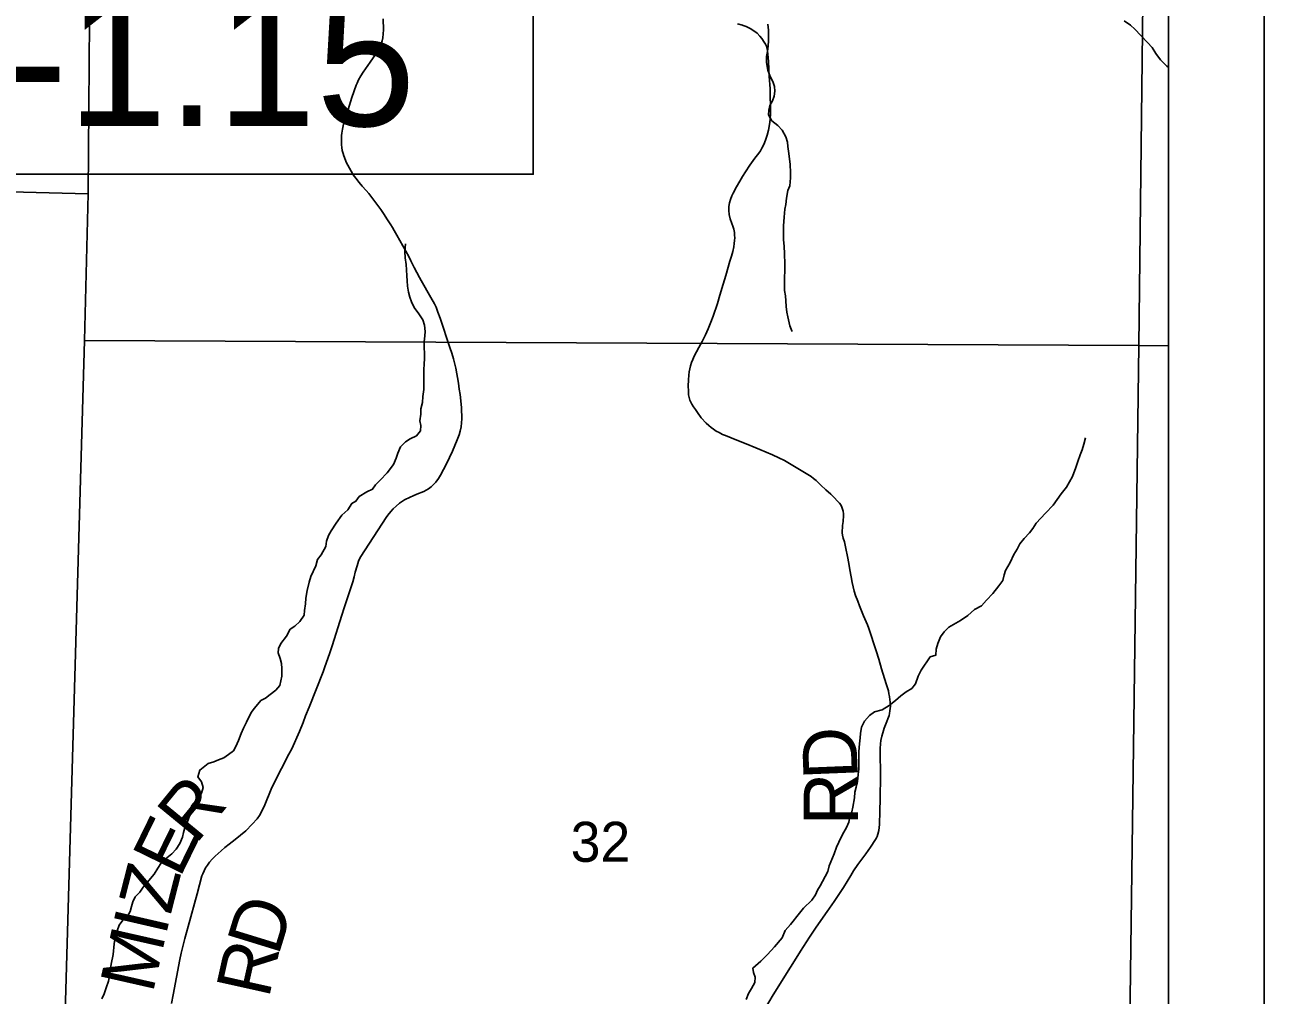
# Model space of a CAD drawing. Extents: x 0 to 34, y 0 to 22.
# Drawn here: x 24.203 to 25.5, y 15.795 to 16.809 of the extents above; entities that cross this region are included whole.
import ezdxf

# ---------------------------------------------------------------- set-up
doc = ezdxf.new("R2010")
doc.units = 0
for name, color, linetype in [('GM_X_Corporation', 7, 'Continuous'), ('GM_X_Minor_River', 7, 'Continuous'), ('GM_X_Section_Text', 7, 'Continuous'), ('GM_X_Township_Road', 7, 'Continuous'), ('GM_X_Township_Road_Text', 7, 'Continuous'), ('SH_Data', 7, 'Continuous'), ('SH_Text', 7, 'Continuous')]:
    doc.layers.add(name, color=color, linetype=linetype)

msp = doc.modelspace()

# ---------------------------------------------------------------- linework, layer by layer
at = {"layer": 'GM_X_Corporation'}
msp.add_lwpolyline([(20.2208, 16.9558), (20.1987, 15.2691), (20.203, 14.81), (20.2016, 14.6512), (20.2571, 14.6508), (21.1282, 14.6279), (21.314, 14.623), (22.3464, 14.612), (22.9003, 14.6033), (24.2301, 14.5912), (24.2265, 14.4444), (24.4406, 14.442), (25.338, 14.4317), (25.4, 14.4307), (25.4, 19.0068)], dxfattribs=at)
for points in [[(23.2763, 17.6399), (24.2773, 17.6357), (24.2765, 17.4936), (24.2698, 16.6327), (23.7676, 16.6453), (23.2579, 16.628)], [(24.2765, 17.4936), (25.3807, 17.4896), (25.3688, 16.474), (24.2658, 16.4792), (24.2698, 16.6327)], [(25.4, 16.4736), (25.4, 17.4893), (25.3807, 17.4896), (25.3688, 16.474)], [(23.2579, 16.628), (23.7676, 16.6453), (24.2698, 16.6327), (24.2658, 16.4792), (24.2407, 15.6067), (23.2418, 15.623)], [(24.2658, 16.4792), (25.3688, 16.474), (25.3552, 15.4512), (24.2392, 15.4615), (24.2407, 15.6067)], [(25.4, 15.4506), (25.4, 16.4736), (25.3688, 16.474), (25.3552, 15.4512)]]:
    msp.add_lwpolyline(points, close=True, dxfattribs=at)
at = {"layer": 'GM_X_Minor_River'}
for points in [[(24.9807, 16.81), (24.9815, 16.8036), (24.9815, 16.7926), (24.9812, 16.7872), (24.9804, 16.7812), (24.9793, 16.7762), (24.9793, 16.7698), (24.9809, 16.7618), (24.9832, 16.7553), (24.9859, 16.75), (24.9878, 16.7447), (24.9882, 16.7398), (24.9874, 16.7348), (24.9855, 16.7299), (24.9829, 16.7249), (24.9818, 16.72), (24.9814, 16.7151), (24.9849, 16.709), (24.9913, 16.7041), (24.9959, 16.6991), (24.9997, 16.6923), (25.0012, 16.6866), (25.0016, 16.682), (25.0024, 16.6771), (25.0032, 16.6718), (25.004, 16.6631), (25.0044, 16.6547), (25.0044, 16.6494), (25.0037, 16.641), (25.0018, 16.6361), (25.0003, 16.6281), (24.9996, 16.6213), (24.9984, 16.6167), (24.9977, 16.6083), (24.997, 16.5992), (24.997, 16.5848), (24.9978, 16.5776), (24.9982, 16.5703), (24.9986, 16.5589), (24.9986, 16.5532), (24.9983, 16.5441), (24.9983, 16.5316), (24.9991, 16.5259), (24.9995, 16.5206), (24.9999, 16.5149), (25.0007, 16.5088), (25.0015, 16.5039), (25.0038, 16.4947), (25.006, 16.4894), (25.0063, 16.4888)], [(25.3535, 16.8133), (25.36, 16.8088), (25.3645, 16.8046), (25.371, 16.7981), (25.3779, 16.7909), (25.3828, 16.7856), (25.3866, 16.7792), (25.3916, 16.7727), (25.3981, 16.7659), (25.4, 16.7647)], [(24.6018, 16.5803), (24.6011, 16.5723), (24.6015, 16.5655), (24.6023, 16.5586), (24.6027, 16.553), (24.6031, 16.5469), (24.6035, 16.5416), (24.6039, 16.5359), (24.6047, 16.5298), (24.6062, 16.5245), (24.6081, 16.5195), (24.6108, 16.5138), (24.6157, 16.507), (24.6199, 16.5009), (24.6215, 16.4952), (24.6222, 16.4888), (24.6219, 16.4842), (24.6211, 16.4778), (24.6212, 16.4721), (24.6216, 16.4652), (24.6216, 16.4607), (24.6212, 16.4542), (24.6209, 16.4493), (24.6209, 16.428), (24.6198, 16.4208), (24.6194, 16.4143), (24.6179, 16.4078), (24.6176, 16.4021), (24.6168, 16.3953), (24.6176, 16.3904), (24.6173, 16.3847), (24.6131, 16.3797), (24.6067, 16.3763), (24.6017, 16.3732), (24.5964, 16.3679), (24.5938, 16.3614), (24.5919, 16.3561), (24.5893, 16.3497), (24.5825, 16.3409), (24.5753, 16.3333), (24.5704, 16.3283), (24.5673, 16.3238), (24.5613, 16.3211), (24.5533, 16.3162), (24.5499, 16.3112), (24.5454, 16.3089), (24.5412, 16.3021), (24.5351, 16.2967), (24.5291, 16.2884), (24.5238, 16.2804), (24.5212, 16.2754), (24.5189, 16.2694), (24.5182, 16.264), (24.5133, 16.2553), (24.5095, 16.2503), (24.508, 16.2435), (24.5027, 16.2325), (24.5008, 16.2264), (24.4989, 16.218), (24.4974, 16.21), (24.4971, 16.204), (24.496, 16.1971), (24.4956, 16.1922), (24.4911, 16.1853), (24.4858, 16.1807), (24.4812, 16.1773), (24.4771, 16.1701), (24.4714, 16.1625), (24.4687, 16.1572), (24.4684, 16.1526), (24.4707, 16.1469), (24.4718, 16.1416), (24.4722, 16.1363), (24.4723, 16.1283), (24.4704, 16.1184), (24.4662, 16.1138), (24.4602, 16.1093), (24.4552, 16.1054), (24.4503, 16.1028), (24.4439, 16.0948), (24.4401, 16.0902), (24.4352, 16.0803), (24.4322, 16.0739), (24.4299, 16.0682), (24.4269, 16.0609), (24.4243, 16.0548), (24.4216, 16.0503), (24.4167, 16.0465), (24.4118, 16.043), (24.4061, 16.0407), (24.4011, 16.0388), (24.3951, 16.0369), (24.3867, 16.0301), (24.3845, 16.0232), (24.3883, 16.0179), (24.3902, 16.0118), (24.3883, 16.0061), (24.3823, 15.9981), (24.3781, 15.9932), (24.3766, 15.9882), (24.3762, 15.9829)], [(25.1615, 16.1694), (25.1653, 16.1747), (25.1702, 16.1796), (25.1824, 16.1865), (25.1899, 16.1918), (25.1971, 16.1979), (25.2043, 16.2017), (25.2096, 16.2078), (25.2161, 16.2147), (25.2225, 16.2227), (25.2266, 16.2284), (25.2278, 16.2341), (25.2293, 16.2386), (25.2342, 16.247), (25.238, 16.2554), (25.2417, 16.2611), (25.2444, 16.2668), (25.2489, 16.2721), (25.2546, 16.2782), (25.258, 16.2828), (25.2614, 16.2881), (25.2712, 16.2987), (25.2792, 16.3071), (25.2875, 16.3189), (25.2932, 16.3258), (25.2996, 16.3372), (25.303, 16.3463), (25.3052, 16.3528), (25.3075, 16.3596), (25.3094, 16.3649), (25.3113, 16.371), (25.3131, 16.3775)], [(24.958, 15.7904), (24.9606, 15.7965), (24.9637, 15.8019), (24.9671, 15.8079), (24.9674, 15.8136), (24.9659, 15.8186), (24.9651, 15.8231), (24.9734, 15.8304), (24.9803, 15.8372), (24.9878, 15.8452), (24.9958, 15.8548), (24.9988, 15.8624), (25.0045, 15.8688), (25.0139, 15.8806), (25.0181, 15.8856), (25.0268, 15.894), (25.0306, 15.8997), (25.0328, 15.9046), (25.0355, 15.9092), (25.0378, 15.9137), (25.0434, 15.924), (25.0449, 15.9301), (25.0502, 15.9426), (25.0525, 15.9495), (25.0551, 15.9548), (25.0589, 15.9628), (25.063, 15.97), (25.0653, 15.9757), (25.0664, 15.9814), (25.0687, 15.9864), (25.0698, 15.9913), (25.0713, 16.0012), (25.0717, 16.0069), (25.0732, 16.0122), (25.0747, 16.0183), (25.0754, 16.0255), (25.0761, 16.0309), (25.0761, 16.0366), (25.0761, 16.0495), (25.0768, 16.0575), (25.0772, 16.0639), (25.0775, 16.0685), (25.0787, 16.075), (25.0817, 16.0814), (25.087, 16.0871), (25.0923, 16.091), (25.1003, 16.0932), (25.1078, 16.0978), (25.1143, 16.1028), (25.12, 16.1077), (25.1253, 16.1119), (25.1313, 16.1153), (25.1351, 16.1203), (25.1381, 16.1283), (25.1411, 16.1347), (25.1506, 16.1484), (25.1566, 16.1503), (25.157, 16.1564), (25.1585, 16.1625), (25.1615, 16.1694)], [(24.3762, 15.9829), (24.3732, 15.9753), (24.371, 15.9696), (24.3695, 15.9647), (24.3683, 15.9601), (24.3657, 15.9533), (24.3619, 15.9475), (24.3574, 15.9426), (24.3521, 15.9384), (24.3456, 15.9323), (24.3426, 15.9277), (24.3388, 15.9213), (24.3316, 15.9125), (24.3271, 15.9076), (24.3237, 15.9026), (24.3188, 15.8977), (24.3165, 15.8923), (24.315, 15.8874), (24.3135, 15.8821), (24.3109, 15.8775), (24.3059, 15.8733), (24.3022, 15.868), (24.2999, 15.8619), (24.298, 15.8554), (24.2969, 15.8486), (24.2958, 15.8372), (24.2939, 15.8273), (24.2928, 15.8201), (24.292, 15.8151), (24.2909, 15.8094), (24.2887, 15.8026), (24.2864, 15.7961), (24.2841, 15.7908)]]:
    msp.add_lwpolyline(points, dxfattribs=at)
at = {"layer": 'GM_X_Township_Road'}
for points in [[(24.357, 15.7861), (24.3585, 15.795), (24.3656, 15.8321), (24.367, 15.8386), (24.3709, 15.8542), (24.3743, 15.8667), (24.3837, 15.9009), (24.3888, 15.9195), (24.3897, 15.9217), (24.391, 15.9248), (24.3926, 15.928), (24.3944, 15.9307), (24.3966, 15.9337), (24.3993, 15.9368), (24.4026, 15.9401), (24.4089, 15.9458), (24.4127, 15.9491), (24.4172, 15.9527), (24.4235, 15.9577), (24.4345, 15.9665), (24.4414, 15.9734), (24.4465, 15.9793), (24.4489, 15.9827), (24.4513, 15.9871), (24.4544, 15.9938), (24.4611, 16.0101), (24.4644, 16.0168), (24.4798, 16.0467), (24.4827, 16.0524), (24.4907, 16.0705), (24.4945, 16.0799), (24.4972, 16.0867), (24.5009, 16.096), (24.5156, 16.133), (24.5174, 16.1379), (24.5222, 16.1518), (24.5249, 16.1601), (24.535, 16.1922), (24.5375, 16.1999), (24.5465, 16.2269), (24.5479, 16.2321), (24.5491, 16.2369), (24.551, 16.2438), (24.5525, 16.2486), (24.554, 16.2515), (24.5551, 16.2535), (24.5815, 16.2941), (24.5833, 16.2966), (24.5865, 16.3006), (24.5889, 16.3032), (24.5918, 16.3061), (24.5953, 16.309), (24.5984, 16.3112), (24.6007, 16.3127), (24.6067, 16.3156), (24.6097, 16.3168), (24.6136, 16.3184), (24.6208, 16.3214), (24.6233, 16.3227), (24.6257, 16.3242), (24.6285, 16.3263), (24.631, 16.3286), (24.6333, 16.3312), (24.6362, 16.3351), (24.6383, 16.3385), (24.6415, 16.3442), (24.6446, 16.3504), (24.6507, 16.3636), (24.6534, 16.3696), (24.6558, 16.3754), (24.6577, 16.3805), (24.6588, 16.3843), (24.6598, 16.3889), (24.6603, 16.393), (24.6606, 16.3973), (24.6603, 16.409), (24.6599, 16.4127), (24.6588, 16.4228), (24.658, 16.4283), (24.6571, 16.4346), (24.6542, 16.4502), (24.6532, 16.4546), (24.6518, 16.4601), (24.6501, 16.4659), (24.6482, 16.472), (24.6378, 16.5026), (24.6356, 16.509), (24.6337, 16.5141), (24.632, 16.5177), (24.6283, 16.5243), (24.6181, 16.5418), (24.6163, 16.5451), (24.6136, 16.5504), (24.6109, 16.5557), (24.6074, 16.5625), (24.6051, 16.567), (24.5927, 16.5894), (24.5898, 16.5943), (24.588, 16.5972), (24.5862, 16.6002), (24.5829, 16.6055), (24.5787, 16.612), (24.5759, 16.6162), (24.5729, 16.6203), (24.5664, 16.6289), (24.5632, 16.6328), (24.5604, 16.636), (24.5565, 16.6406), (24.5533, 16.6444), (24.5498, 16.6488), (24.5471, 16.6525), (24.5448, 16.6561), (24.5413, 16.6624), (24.54, 16.6651), (24.5372, 16.6722), (24.5364, 16.6749), (24.5356, 16.6779), (24.5351, 16.6811), (24.5348, 16.6839), (24.5346, 16.6871), (24.5349, 16.6935), (24.5352, 16.696), (24.5357, 16.7002), (24.5366, 16.7037), (24.5373, 16.7068), (24.5386, 16.7114), (24.5416, 16.7206), (24.5457, 16.7332), (24.5501, 16.7462), (24.551, 16.7483), (24.5525, 16.7516), (24.5548, 16.7559), (24.5573, 16.7599), (24.5646, 16.7702), (24.5678, 16.7747), (24.5725, 16.7813), (24.5741, 16.784), (24.5756, 16.787), (24.5764, 16.7892), (24.5773, 16.7924), (24.578, 16.7957), (24.5784, 16.7998), (24.5786, 16.8041), (24.5782, 16.8154)], [(24.9855, 16.3596), (24.9723, 16.3653), (24.9683, 16.367), (24.9582, 16.3711), (24.9482, 16.3751), (24.9363, 16.3799), (24.9333, 16.3811), (24.9297, 16.3829), (24.9267, 16.3846), (24.9239, 16.3865), (24.9215, 16.3884), (24.919, 16.3903), (24.9163, 16.3929), (24.9111, 16.3985), (24.9071, 16.4038), (24.9049, 16.4071), (24.9031, 16.4098), (24.9014, 16.4126), (24.9, 16.4154), (24.8993, 16.417), (24.8983, 16.4195), (24.8979, 16.4223), (24.8976, 16.4265), (24.8975, 16.4314), (24.8976, 16.438), (24.898, 16.443), (24.8985, 16.4463), (24.899, 16.4497), (24.8999, 16.4528), (24.9009, 16.4562), (24.9022, 16.4595), (24.9035, 16.4628), (24.9062, 16.4674), (24.9087, 16.472), (24.9121, 16.4783), (24.9154, 16.4852), (24.9183, 16.4915), (24.9212, 16.4983), (24.9237, 16.5045), (24.9282, 16.5178), (24.9306, 16.5267), (24.9339, 16.538), (24.9367, 16.5472), (24.9411, 16.562), (24.9428, 16.5675), (24.9441, 16.5722), (24.9451, 16.5771), (24.9456, 16.5807), (24.946, 16.5838), (24.9461, 16.5864), (24.946, 16.5894), (24.9458, 16.5923), (24.9451, 16.5955), (24.9441, 16.5988), (24.9431, 16.6015), (24.9415, 16.6064), (24.9404, 16.611), (24.9398, 16.615), (24.94, 16.6193), (24.9407, 16.623), (24.9417, 16.6268), (24.943, 16.6304), (24.9444, 16.6334), (24.9479, 16.6398), (24.9513, 16.6457), (24.9543, 16.6508), (24.9572, 16.6556), (24.9619, 16.6627), (24.9672, 16.6698), (24.9713, 16.6752), (24.973, 16.6776), (24.9744, 16.6803), (24.9764, 16.6842), (24.9783, 16.6888), (24.9802, 16.694), (24.9815, 16.6993), (24.9825, 16.7049), (24.983, 16.7102), (24.9835, 16.7169), (24.983, 16.7424), (24.9823, 16.7556), (24.9815, 16.7704), (24.9812, 16.7752), (24.9808, 16.7785), (24.9804, 16.7818), (24.9799, 16.7846), (24.9792, 16.7869), (24.9782, 16.7892), (24.977, 16.7913), (24.9744, 16.795), (24.9724, 16.7975), (24.9694, 16.8004), (24.9661, 16.8029), (24.9621, 16.8055), (24.9579, 16.8075), (24.9551, 16.8086)], [(24.9551, 16.8086), (24.9542, 16.809), (24.9491, 16.8103)], [(25.0043, 15.824), (25.0085, 15.8307), (25.0149, 15.8408), (25.0244, 15.8553), (25.0305, 15.8647), (25.0363, 15.8729), (25.0429, 15.8823), (25.0502, 15.8928), (25.06, 15.9075), (25.0675, 15.92), (25.0705, 15.9248), (25.0749, 15.9314), (25.0832, 15.9426), (25.0881, 15.9494), (25.0935, 15.9575), (25.0944, 15.9592), (25.0951, 15.9608), (25.0959, 15.9632), (25.0967, 15.9671), (25.0975, 15.9732), (25.0977, 15.9765), (25.098, 15.9839), (25.0981, 16.0033), (25.0985, 16.0213), (25.0983, 16.0526), (25.0986, 16.0574), (25.099, 16.0612), (25.1, 16.0657), (25.1011, 16.069), (25.1026, 16.074), (25.1053, 16.081), (25.1063, 16.0837), (25.1075, 16.0871), (25.1081, 16.0894), (25.1085, 16.0919), (25.1088, 16.0945), (25.1089, 16.0971), (25.1087, 16.1014), (25.1085, 16.1034), (25.1079, 16.1069), (25.1074, 16.1098), (25.1068, 16.1128), (25.1046, 16.1203), (25.0998, 16.1358), (25.0967, 16.1462), (25.0941, 16.1547), (25.0864, 16.1782), (25.0849, 16.1821), (25.0809, 16.1913), (25.0765, 16.202), (25.0748, 16.2067), (25.0725, 16.2128), (25.071, 16.2173), (25.0699, 16.2216), (25.0689, 16.2263), (25.0679, 16.2322), (25.0666, 16.2394), (25.0654, 16.2462), (25.0641, 16.2535), (25.0624, 16.2618), (25.0608, 16.2687), (25.0597, 16.2724), (25.059, 16.2757), (25.0586, 16.2783), (25.0588, 16.2859), (25.0594, 16.2901), (25.0599, 16.2961), (25.0598, 16.2981), (25.0594, 16.3007), (25.0589, 16.3028), (25.0581, 16.3051), (25.057, 16.3073), (25.0557, 16.3091), (25.0533, 16.3117), (25.0503, 16.3147), (25.0466, 16.3184), (25.0415, 16.323), (25.0363, 16.328), (25.0312, 16.3327), (25.0285, 16.335), (25.0259, 16.3369), (25.0225, 16.3391), (25.014, 16.3445), (25.0053, 16.3496), (24.9981, 16.3537), (24.9921, 16.3567), (24.9855, 16.3596)], [(24.9771, 15.7799), (24.9863, 15.7953), (25.0043, 15.824)]]:
    msp.add_lwpolyline(points, dxfattribs=at)
at = {"layer": 'SH_Data'}
for points in [[(18.5, 20.5), (25.5, 20.5), (25.5, 13.5), (18.5, 13.5)], [(18.6, 20.4), (25.4, 20.4), (25.4, 13.6), (18.6, 13.6)]]:
    msp.add_lwpolyline(points, close=True, dxfattribs=at)
at = {"layer": 'SH_Text'}
msp.add_lwpolyline([(23.3742, 16.893), (23.3742, 16.653), (24.7353, 16.653), (24.7353, 16.893)], close=True, dxfattribs=at)

# ---------------------------------------------------------------- texts
at = {"layer": 'GM_X_Section_Text'}
msp.add_text('32', height=0.04186, rotation=0, dxfattribs=at).set_placement((24.7745, 15.9342))
at = {"layer": 'GM_X_Township_Road_Text'}
for s, rotation, p in [('D', 92.2974, (25.075, 16.0215)), ('R', 50.6337, (24.3822, 15.9516)), ('R', 90.0429, (25.0751, 15.9725)), ('E', 63.9697, (24.3655, 15.9163)), ('Z', 75.6041, (24.3559, 15.878)), ('D', 72.9072, (24.4685, 15.8348)), ('I', 77.0089, (24.3508, 15.8556)), ('M', 77.2447, (24.3372, 15.7956)), ('R', 77.4377, (24.4586, 15.7904))]:
    msp.add_text(s, height=0.0568, rotation=rotation, dxfattribs=at).set_placement(p)
at = {"layer": 'SH_Text'}
msp.add_text('HAS-646-1.15', height=0.14, dxfattribs=at).set_placement((23.426, 16.7035))

doc.saveas('drawing.dxf')
